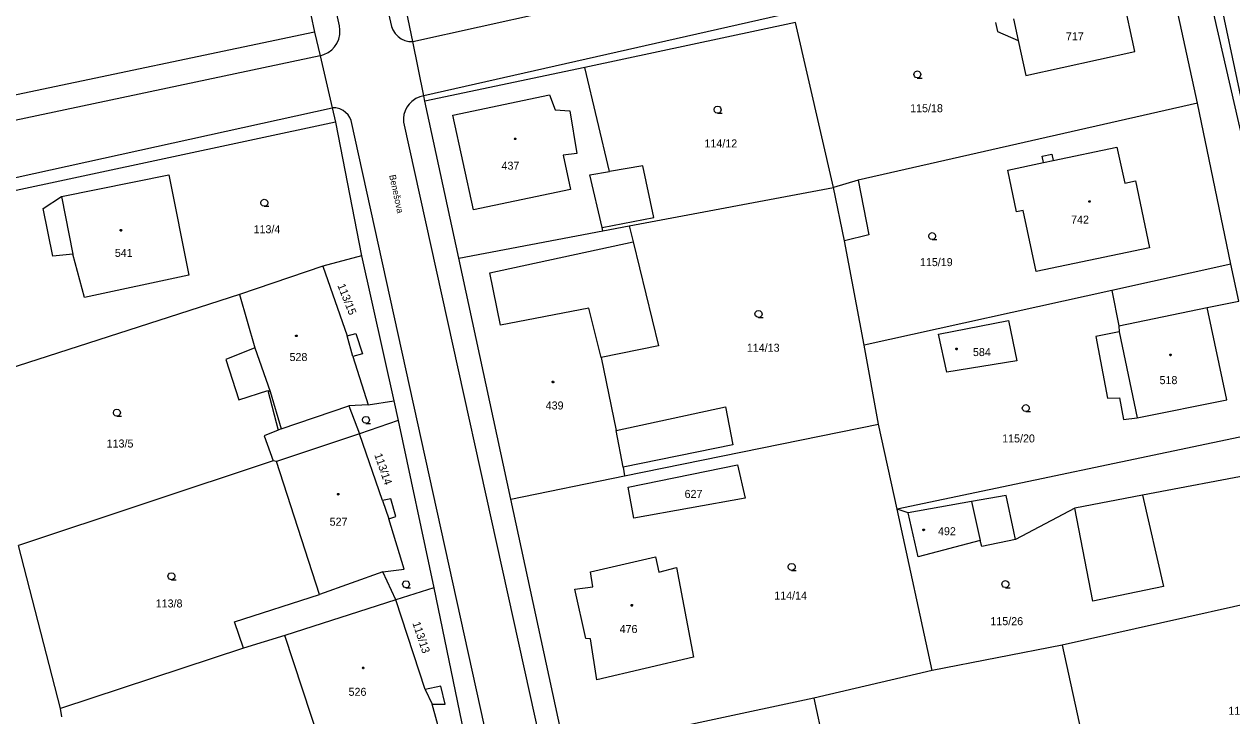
# Model space of a CAD drawing. Extents: x -757994 to -755874, y -1047691 to -1046119.
# Drawn here: x -756409.1 to -756280.8, y -1046951.8 to -1046878.4 of the extents above; entities that cross this region are included whole.
import ezdxf

# ---------------------------------------------------------------- set-up
doc = ezdxf.new("R2010")
doc.units = 0
doc.layers.add('katastrální mapa', color=7, linetype='Continuous')

msp = doc.modelspace()

# ---------------------------------------------------------------- linework, layer by layer
at = {"layer": 'katastrální mapa'}
for p, q in [((-756310.63, -1046740.64), (-756269.78, -1046934.1)), ((-756393.26, -1046773.82), (-756370.08, -1046878.6)), ((-756375.61, -1046878.54), (-756398, -1046775.71)), ((-756289.01, -1046849.81), (-756269.04, -1046937.62)), ((-756367.82, -1046880.2), (-756289.56, -1046862.86)), ((-756288.48, -1046868.3), (-756366.64, -1046885.96)), ((-756284.47, -1046886.76), (-756288.21, -1046869.66)), ((-756291.13, -1046881.27), (-756293.02, -1046872.66)), ((-756379.28, -1046874.3), (-756378.24, -1046879.22)), ((-756367.82, -1046880.2), (-756368.48, -1046876.97)), ((-756304.02, -1046877.8), (-756303.52, -1046880.1)), ((-756378.24, -1046879.22), (-756414.68, -1046886.88)), ((-756378.24, -1046879.22), (-756377.66, -1046881.72)), ((-756327.17, -1046878.19), (-756349.56, -1046882.95)), ((-756323.13, -1046895.69), (-756327.17, -1046878.19)), ((-756305.94, -1046878.2), (-756305.74, -1046879.13)), ((-756305.74, -1046879.13), (-756303.52, -1046880.1)), ((-756366.64, -1046885.96), (-756367.82, -1046880.2)), ((-756303.52, -1046880.1), (-756302.71, -1046883.81)), ((-756377.66, -1046881.72), (-756455.39, -1046898.22)), ((-756377.66, -1046881.72), (-756376.38, -1046887.23)), ((-756302.71, -1046883.81), (-756291.13, -1046881.27)), ((-756349.56, -1046882.95), (-756366.52, -1046886.55)), ((-756346.94, -1046894.01), (-756349.56, -1046882.95)), ((-756366.52, -1046886.55), (-756366.64, -1046885.96)), ((-756362.92, -1046903.22), (-756366.52, -1046886.55)), ((-756363.56, -1046888.02), (-756353.29, -1046885.85)), ((-756353.29, -1046885.85), (-756352.71, -1046887.45)), ((-756284.47, -1046886.76), (-756320.52, -1046894.94)), ((-756280.96, -1046903.84), (-756284.47, -1046886.76)), ((-756453.94, -1046904.33), (-756376.38, -1046887.23)), ((-756376.38, -1046887.23), (-756376.03, -1046888.76)), ((-756361.38, -1046898.09), (-756363.56, -1046888.02)), ((-756352.71, -1046887.45), (-756351.15, -1046887.55)), ((-756351.15, -1046887.55), (-756350.39, -1046892.08)), ((-756376.03, -1046888.76), (-756414.65, -1046897.03)), ((-756376.03, -1046888.76), (-756373.27, -1046902.96)), ((-756352.31, -1046988.69), (-756374.35, -1046888.59)), ((-756368.81, -1046888.76), (-756346.03, -1046991.81)), ((-756350.39, -1046892.08), (-756351.85, -1046892.27)), ((-756299.81, -1046892.85), (-756293.06, -1046891.43)), ((-756293.06, -1046891.43), (-756292.21, -1046895.24)), ((-756351.85, -1046892.27), (-756351.07, -1046895.92)), ((-756343.38, -1046893.4), (-756346.94, -1046894.01)), ((-756342.2, -1046898.88), (-756343.38, -1046893.4)), ((-756304.64, -1046893.86), (-756300.83, -1046893.06)), ((-756300.98, -1046892.37), (-756299.96, -1046892.15)), ((-756300.83, -1046893.06), (-756300.98, -1046892.37)), ((-756300.83, -1046893.06), (-756299.81, -1046892.85)), ((-756299.96, -1046892.15), (-756299.81, -1046892.85)), ((-756405.13, -1046896.65), (-756393.73, -1046894.36)), ((-756393.73, -1046894.36), (-756391.59, -1046905.02)), ((-756349.01, -1046894.37), (-756346.94, -1046894.01)), ((-756347.71, -1046899.94), (-756349.01, -1046894.37)), ((-756303.69, -1046898.29), (-756304.64, -1046893.86)), ((-756351.07, -1046895.92), (-756361.38, -1046898.09)), ((-756344.82, -1046899.79), (-756323.13, -1046895.69)), ((-756320.52, -1046894.94), (-756323.13, -1046895.69)), ((-756321.96, -1046901.38), (-756323.13, -1046895.69)), ((-756320.52, -1046894.94), (-756319.39, -1046900.73)), ((-756292.21, -1046895.24), (-756291.08, -1046895)), ((-756291.08, -1046895), (-756289.58, -1046902.11)), ((-756407.05, -1046897.94), (-756405.13, -1046896.65)), ((-756405.13, -1046896.65), (-756403.91, -1046902.78)), ((-756406.05, -1046903.01), (-756407.05, -1046897.94)), ((-756303, -1046898.14), (-756303.69, -1046898.29)), ((-756301.63, -1046904.61), (-756303, -1046898.14)), ((-756347.71, -1046899.94), (-756342.2, -1046898.88)), ((-756347.62, -1046900.32), (-756344.82, -1046899.79)), ((-756344.82, -1046899.79), (-756344.41, -1046901.47)), ((-756362.92, -1046903.22), (-756347.62, -1046900.32)), ((-756347.62, -1046900.32), (-756347.71, -1046899.94)), ((-756319.39, -1046900.73), (-756321.96, -1046901.38)), ((-756359.64, -1046904.77), (-756344.41, -1046901.47)), ((-756344.41, -1046901.47), (-756341.72, -1046912.53)), ((-756319.88, -1046912.45), (-756321.96, -1046901.38)), ((-756289.58, -1046902.11), (-756301.63, -1046904.61)), ((-756403.91, -1046902.78), (-756406.05, -1046903.01)), ((-756402.67, -1046907.39), (-756403.91, -1046902.78)), ((-756373.27, -1046902.96), (-756377.38, -1046904.07)), ((-756373.27, -1046902.96), (-756369.84, -1046918.35)), ((-756357.39, -1046928.78), (-756362.92, -1046903.22)), ((-756377.38, -1046904.07), (-756386.22, -1046907.08)), ((-756377.38, -1046904.07), (-756374.79, -1046911.44)), ((-756358.5, -1046910.33), (-756359.64, -1046904.77)), ((-756280.96, -1046903.84), (-756293.57, -1046906.63)), ((-756280.1, -1046907.77), (-756280.96, -1046903.84)), ((-756391.59, -1046905.02), (-756402.67, -1046907.39)), ((-756386.22, -1046907.08), (-756414.19, -1046916.08)), ((-756386.22, -1046907.08), (-756384.57, -1046912.72)), ((-756293.57, -1046906.63), (-756319.88, -1046912.45)), ((-756293.57, -1046906.63), (-756292.83, -1046910.39)), ((-756349.13, -1046908.5), (-756358.5, -1046910.33)), ((-756347.81, -1046913.76), (-756349.13, -1046908.5)), ((-756292.83, -1046910.39), (-756283.45, -1046908.46)), ((-756283.45, -1046908.46), (-756280.1, -1046907.77)), ((-756281.37, -1046918.24), (-756283.45, -1046908.46)), ((-756312, -1046911.29), (-756304.57, -1046909.82)), ((-756304.57, -1046909.82), (-756303.68, -1046914.09)), ((-756374.79, -1046911.44), (-756373.86, -1046911.21)), ((-756373.86, -1046911.21), (-756373.15, -1046913.35)), ((-756311.12, -1046915.31), (-756312, -1046911.29)), ((-756292.79, -1046911.04), (-756295.3, -1046911.53)), ((-756292.83, -1046910.39), (-756292.79, -1046911.04)), ((-756292.79, -1046911.04), (-756290.91, -1046920.17)), ((-756374.17, -1046913.64), (-756374.79, -1046911.44)), ((-756341.72, -1046912.53), (-756347.81, -1046913.76)), ((-756318.36, -1046920.83), (-756319.88, -1046912.45)), ((-756295.3, -1046911.53), (-756294.03, -1046918.06)), ((-756384.57, -1046912.72), (-756387.65, -1046913.96)), ((-756384.57, -1046912.72), (-756382.94, -1046917.35)), ((-756373.15, -1046913.35), (-756374.17, -1046913.64)), ((-756374.17, -1046913.64), (-756372.56, -1046918.78)), ((-756347.81, -1046913.76), (-756346.21, -1046921.5)), ((-756387.65, -1046913.96), (-756386.27, -1046918.25)), ((-756303.68, -1046914.09), (-756311.12, -1046915.31)), ((-756386.27, -1046918.25), (-756383.22, -1046917.27)), ((-756383.22, -1046917.27), (-756382.09, -1046921.47)), ((-756383.22, -1046917.27), (-756382.94, -1046917.35)), ((-756382.94, -1046917.35), (-756381.78, -1046921.34)), ((-756381.78, -1046921.34), (-756374.6, -1046918.9)), ((-756372.56, -1046918.78), (-756374.6, -1046918.9)), ((-756374.6, -1046918.9), (-756373.48, -1046921.86)), ((-756372.56, -1046918.78), (-756369.84, -1046918.35)), ((-756369.84, -1046918.35), (-756369.38, -1046920.43)), ((-756346.21, -1046921.5), (-756334.59, -1046918.98)), ((-756334.59, -1046918.98), (-756333.84, -1046923.03)), ((-756294.03, -1046918.06), (-756292.78, -1046918.02)), ((-756292.78, -1046918.02), (-756292.36, -1046920.32)), ((-756290.91, -1046920.17), (-756281.37, -1046918.24)), ((-756292.36, -1046920.32), (-756290.91, -1046920.17)), ((-756382.09, -1046921.47), (-756383.59, -1046922.06)), ((-756381.78, -1046921.34), (-756382.09, -1046921.47)), ((-756369.38, -1046920.43), (-756373.48, -1046921.86)), ((-756369.38, -1046920.43), (-756365.56, -1046938.21)), ((-756345.49, -1046925.39), (-756346.21, -1046921.5)), ((-756345.32, -1046926.32), (-756318.36, -1046920.83)), ((-756316.39, -1046929.84), (-756318.36, -1046920.83)), ((-756277.09, -1046921.59), (-756316.39, -1046929.84)), ((-756383.59, -1046922.06), (-756382.63, -1046924.73)), ((-756373.48, -1046921.86), (-756382.27, -1046924.8)), ((-756371.03, -1046928.94), (-756373.48, -1046921.86)), ((-756333.84, -1046923.03), (-756345.49, -1046925.39)), ((-756382.63, -1046924.73), (-756409.67, -1046933.7)), ((-756382.27, -1046924.8), (-756382.63, -1046924.73)), ((-756377.7, -1046938.9), (-756382.27, -1046924.8)), ((-756345.49, -1046925.39), (-756345.32, -1046926.32)), ((-756344.94, -1046927.52), (-756333.33, -1046925.14)), ((-756333.33, -1046925.14), (-756332.51, -1046928.69)), ((-756357.39, -1046928.78), (-756345.32, -1046926.32)), ((-756276.17, -1046925.69), (-756290.34, -1046928.38)), ((-756344.34, -1046930.8), (-756344.94, -1046927.52)), ((-756370.14, -1046928.75), (-756371.03, -1046928.94)), ((-756371.03, -1046928.94), (-756370.35, -1046930.87)), ((-756369.62, -1046930.63), (-756370.14, -1046928.75)), ((-756351.61, -1046955.54), (-756357.39, -1046928.78)), ((-756332.51, -1046928.69), (-756344.34, -1046930.8)), ((-756308.49, -1046929.05), (-756315.21, -1046930.24)), ((-756304.81, -1046928.4), (-756308.49, -1046929.05)), ((-756308.49, -1046929.05), (-756307.56, -1046933.17)), ((-756303.99, -1046932.23), (-756304.81, -1046928.4)), ((-756290.34, -1046928.38), (-756297.51, -1046929.74)), ((-756290.34, -1046928.38), (-756288.09, -1046938.05)), ((-756315.21, -1046930.24), (-756316.39, -1046929.84)), ((-756312.65, -1046946.99), (-756316.39, -1046929.84)), ((-756314.15, -1046934.91), (-756315.21, -1046930.24)), ((-756297.51, -1046929.74), (-756303.81, -1046933.07)), ((-756295.61, -1046939.63), (-756297.51, -1046929.74)), ((-756370.35, -1046930.87), (-756369.62, -1046930.63)), ((-756368.72, -1046936.21), (-756370.35, -1046930.87)), ((-756303.81, -1046933.07), (-756307.39, -1046933.81)), ((-756303.81, -1046933.07), (-756303.99, -1046932.23)), ((-756405.21, -1046951.01), (-756409.67, -1046933.7)), ((-756307.56, -1046933.17), (-756314.15, -1046934.91)), ((-756307.39, -1046933.81), (-756307.56, -1046933.17)), ((-756348.94, -1046936.52), (-756342.03, -1046934.9)), ((-756342.03, -1046934.9), (-756341.69, -1046936.53)), ((-756371, -1046936.5), (-756377.7, -1046938.9)), ((-756371, -1046936.5), (-756368.72, -1046936.21)), ((-756369.6, -1046939.49), (-756371, -1046936.5)), ((-756348.68, -1046938.09), (-756348.94, -1046936.52)), ((-756341.69, -1046936.53), (-756339.82, -1046936.05)), ((-756339.82, -1046936.05), (-756338.01, -1046945.57)), ((-756365.56, -1046938.21), (-756369.6, -1046939.49)), ((-756365.56, -1046938.21), (-756361.96, -1046955.74)), ((-756350.62, -1046938.34), (-756348.68, -1046938.09)), ((-756288.09, -1046938.05), (-756295.61, -1046939.63)), ((-756386.73, -1046941.82), (-756377.7, -1046938.9)), ((-756369.6, -1046939.49), (-756381.41, -1046943.28)), ((-756366.51, -1046949), (-756369.6, -1046939.49)), ((-756349.42, -1046943.58), (-756350.62, -1046938.34)), ((-756273.27, -1046938.57), (-756298.86, -1046944.31)), ((-756385.78, -1046944.6), (-756386.73, -1046941.82)), ((-756381.41, -1046943.28), (-756385.78, -1046944.6)), ((-756376.83, -1046957.1), (-756381.41, -1046943.28)), ((-756385.78, -1046944.6), (-756405.21, -1046951.01)), ((-756348.94, -1046943.61), (-756349.42, -1046943.58)), ((-756348.26, -1046947.98), (-756348.94, -1046943.61)), ((-756298.86, -1046944.31), (-756312.65, -1046946.99)), ((-756298.86, -1046944.31), (-756294.36, -1046964.81)), ((-756338.01, -1046945.57), (-756348.26, -1046947.98)), ((-756312.65, -1046946.99), (-756325.22, -1046949.93)), ((-756364.84, -1046948.64), (-756366.51, -1046949)), ((-756366.51, -1046949), (-756365.76, -1046950.54)), ((-756364.36, -1046950.54), (-756364.84, -1046948.64)), ((-756405.07, -1046951.9), (-756405.21, -1046951.01)), ((-756364.88, -1046953.79), (-756365.76, -1046950.54)), ((-756365.76, -1046950.54), (-756364.36, -1046950.54)), ((-756325.22, -1046949.93), (-756351.61, -1046955.54)), ((-756325.22, -1046949.93), (-756317.82, -1046983.8))]:
    msp.add_line(p, q, dxfattribs=at)
for points in [[(-756377.66, -1046881.72), (-756377.24, -1046881.6), (-756376.8, -1046881.38), (-756376.41, -1046881.08), (-756376.12, -1046880.76), (-756375.87, -1046880.4), (-756375.68, -1046879.95), (-756375.57, -1046879.47), (-756375.55, -1046878.97), (-756375.61, -1046878.54)], [(-756370.08, -1046878.6), (-756369.94, -1046878.98), (-756369.7, -1046879.37), (-756369.38, -1046879.69), (-756369.04, -1046879.92), (-756368.67, -1046880.09), (-756368.23, -1046880.19), (-756367.82, -1046880.2)], [(-756314.23, -1046884.07), (-756314.42, -1046884.02), (-756314.55, -1046883.89), (-756314.6, -1046883.7), (-756314.55, -1046883.51), (-756314.42, -1046883.38), (-756314.23, -1046883.33), (-756314.05, -1046883.38), (-756313.92, -1046883.51), (-756313.86, -1046883.71), (-756313.92, -1046883.9), (-756314.05, -1046884.03), (-756314.24, -1046884.08), (-756313.74, -1046884.08)], [(-756366.64, -1046885.96), (-756367.06, -1046886.07), (-756367.5, -1046886.27), (-756367.9, -1046886.56), (-756368.2, -1046886.87), (-756368.44, -1046887.19), (-756368.62, -1046887.56), (-756368.75, -1046887.95), (-756368.81, -1046888.36), (-756368.81, -1046888.76)], [(-756374.35, -1046888.59), (-756374.49, -1046888.27), (-756374.69, -1046887.98), (-756374.94, -1046887.73), (-756375.22, -1046887.53), (-756375.57, -1046887.35), (-756375.99, -1046887.25), (-756376.38, -1046887.23)], [(-756335.44, -1046887.81), (-756335.63, -1046887.76), (-756335.76, -1046887.62), (-756335.82, -1046887.44), (-756335.76, -1046887.26), (-756335.63, -1046887.12), (-756335.45, -1046887.07), (-756335.26, -1046887.12), (-756335.12, -1046887.26), (-756335.08, -1046887.45), (-756335.12, -1046887.64), (-756335.26, -1046887.77), (-756335.45, -1046887.82), (-756334.95, -1046887.82)], [(-756383.57, -1046897.69), (-756383.76, -1046897.64), (-756383.9, -1046897.5), (-756383.95, -1046897.32), (-756383.9, -1046897.14), (-756383.76, -1046897), (-756383.58, -1046896.95), (-756383.39, -1046897), (-756383.25, -1046897.14), (-756383.21, -1046897.33), (-756383.25, -1046897.51), (-756383.39, -1046897.65), (-756383.58, -1046897.7), (-756383.08, -1046897.7)], [(-756312.65, -1046901.23), (-756312.84, -1046901.18), (-756312.98, -1046901.04), (-756313.03, -1046900.86), (-756312.98, -1046900.68), (-756312.84, -1046900.54), (-756312.66, -1046900.49), (-756312.47, -1046900.54), (-756312.34, -1046900.68), (-756312.29, -1046900.87), (-756312.34, -1046901.05), (-756312.47, -1046901.19), (-756312.66, -1046901.24), (-756312.16, -1046901.24)], [(-756331.1, -1046909.5), (-756331.29, -1046909.45), (-756331.43, -1046909.32), (-756331.48, -1046909.13), (-756331.43, -1046908.95), (-756331.29, -1046908.81), (-756331.1, -1046908.76), (-756330.92, -1046908.81), (-756330.78, -1046908.95), (-756330.73, -1046909.14), (-756330.78, -1046909.33), (-756330.92, -1046909.46), (-756331.11, -1046909.51), (-756330.61, -1046909.51)], [(-756302.71, -1046919.49), (-756302.9, -1046919.44), (-756303.03, -1046919.3), (-756303.09, -1046919.12), (-756303.03, -1046918.94), (-756302.9, -1046918.8), (-756302.72, -1046918.75), (-756302.53, -1046918.8), (-756302.4, -1046918.94), (-756302.35, -1046919.12), (-756302.4, -1046919.32), (-756302.53, -1046919.45), (-756302.72, -1046919.5), (-756302.22, -1046919.5)], [(-756399.23, -1046919.98), (-756399.42, -1046919.93), (-756399.55, -1046919.79), (-756399.6, -1046919.61), (-756399.55, -1046919.43), (-756399.42, -1046919.29), (-756399.23, -1046919.24), (-756399.05, -1046919.29), (-756398.92, -1046919.43), (-756398.86, -1046919.62), (-756398.92, -1046919.8), (-756399.05, -1046919.94), (-756399.24, -1046919.99), (-756398.74, -1046919.99)], [(-756372.78, -1046920.74), (-756372.97, -1046920.69), (-756373.1, -1046920.55), (-756373.16, -1046920.37), (-756373.1, -1046920.19), (-756372.97, -1046920.05), (-756372.79, -1046920), (-756372.6, -1046920.05), (-756372.47, -1046920.19), (-756372.42, -1046920.38), (-756372.47, -1046920.57), (-756372.6, -1046920.7), (-756372.79, -1046920.75), (-756372.29, -1046920.75)], [(-756327.58, -1046936.35), (-756327.77, -1046936.3), (-756327.91, -1046936.17), (-756327.96, -1046935.98), (-756327.91, -1046935.79), (-756327.77, -1046935.66), (-756327.59, -1046935.61), (-756327.4, -1046935.66), (-756327.26, -1046935.79), (-756327.22, -1046935.99), (-756327.26, -1046936.18), (-756327.4, -1046936.31), (-756327.59, -1046936.36), (-756327.09, -1046936.36)], [(-756393.44, -1046937.34), (-756393.63, -1046937.29), (-756393.76, -1046937.16), (-756393.82, -1046936.97), (-756393.76, -1046936.78), (-756393.63, -1046936.65), (-756393.45, -1046936.6), (-756393.26, -1046936.65), (-756393.12, -1046936.78), (-756393.08, -1046936.98), (-756393.12, -1046937.17), (-756393.26, -1046937.3), (-756393.45, -1046937.35), (-756392.95, -1046937.35)], [(-756368.53, -1046938.2), (-756368.72, -1046938.15), (-756368.85, -1046938.01), (-756368.91, -1046937.83), (-756368.85, -1046937.65), (-756368.72, -1046937.51), (-756368.54, -1046937.46), (-756368.35, -1046937.51), (-756368.22, -1046937.65), (-756368.17, -1046937.84), (-756368.22, -1046938.02), (-756368.35, -1046938.16), (-756368.54, -1046938.21), (-756368.04, -1046938.21)], [(-756304.88, -1046938.18), (-756305.07, -1046938.13), (-756305.21, -1046938), (-756305.26, -1046937.81), (-756305.21, -1046937.62), (-756305.07, -1046937.49), (-756304.89, -1046937.44), (-756304.7, -1046937.49), (-756304.57, -1046937.62), (-756304.52, -1046937.82), (-756304.57, -1046938.01), (-756304.7, -1046938.14), (-756304.89, -1046938.19), (-756304.39, -1046938.19)]]:
    msp.add_lwpolyline(points, dxfattribs=at)
for points in [[(-756356.95, -1046890.45), (-756356.9, -1046890.46), (-756356.88, -1046890.5), (-756356.86, -1046890.53), (-756356.88, -1046890.58), (-756356.92, -1046890.61), (-756356.95, -1046890.62), (-756356.99, -1046890.6), (-756357.02, -1046890.57), (-756357.03, -1046890.53), (-756357.02, -1046890.49), (-756356.98, -1046890.45)], [(-756295.95, -1046897.11), (-756295.9, -1046897.12), (-756295.88, -1046897.16), (-756295.86, -1046897.19), (-756295.88, -1046897.23), (-756295.92, -1046897.27), (-756295.95, -1046897.27), (-756295.99, -1046897.26), (-756296.02, -1046897.23), (-756296.03, -1046897.19), (-756296.02, -1046897.15), (-756295.98, -1046897.11)], [(-756398.8, -1046900.17), (-756398.75, -1046900.18), (-756398.73, -1046900.22), (-756398.72, -1046900.25), (-756398.73, -1046900.29), (-756398.77, -1046900.33), (-756398.8, -1046900.34), (-756398.85, -1046900.32), (-756398.88, -1046900.29), (-756398.89, -1046900.25), (-756398.88, -1046900.21), (-756398.84, -1046900.17)], [(-756380.17, -1046911.37), (-756380.12, -1046911.38), (-756380.1, -1046911.42), (-756380.09, -1046911.45), (-756380.1, -1046911.49), (-756380.14, -1046911.53), (-756380.17, -1046911.53), (-756380.22, -1046911.52), (-756380.25, -1046911.49), (-756380.26, -1046911.45), (-756380.25, -1046911.41), (-756380.21, -1046911.37)], [(-756310.06, -1046912.76), (-756310.01, -1046912.77), (-756309.99, -1046912.82), (-756309.98, -1046912.85), (-756309.99, -1046912.9), (-756310.03, -1046912.93), (-756310.06, -1046912.94), (-756310.1, -1046912.92), (-756310.14, -1046912.89), (-756310.15, -1046912.85), (-756310.14, -1046912.8), (-756310.1, -1046912.77)], [(-756287.35, -1046913.4), (-756287.3, -1046913.41), (-756287.27, -1046913.45), (-756287.26, -1046913.48), (-756287.27, -1046913.52), (-756287.32, -1046913.56), (-756287.35, -1046913.57), (-756287.4, -1046913.55), (-756287.43, -1046913.52), (-756287.44, -1046913.48), (-756287.43, -1046913.44), (-756287.39, -1046913.4)], [(-756352.93, -1046916.26), (-756352.88, -1046916.27), (-756352.85, -1046916.32), (-756352.85, -1046916.35), (-756352.85, -1046916.4), (-756352.9, -1046916.43), (-756352.93, -1046916.44), (-756352.98, -1046916.42), (-756353.01, -1046916.39), (-756353.02, -1046916.35), (-756353.01, -1046916.3), (-756352.97, -1046916.27)], [(-756375.73, -1046928.19), (-756375.68, -1046928.2), (-756375.66, -1046928.24), (-756375.65, -1046928.27), (-756375.66, -1046928.32), (-756375.7, -1046928.35), (-756375.73, -1046928.36), (-756375.77, -1046928.34), (-756375.8, -1046928.31), (-756375.82, -1046928.27), (-756375.8, -1046928.23), (-756375.76, -1046928.19)], [(-756313.57, -1046931.97), (-756313.52, -1046931.98), (-756313.49, -1046932.02), (-756313.48, -1046932.05), (-756313.49, -1046932.1), (-756313.53, -1046932.13), (-756313.57, -1046932.14), (-756313.61, -1046932.12), (-756313.65, -1046932.09), (-756313.66, -1046932.05), (-756313.65, -1046932.01), (-756313.6, -1046931.97)], [(-756344.54, -1046939.98), (-756344.49, -1046939.99), (-756344.47, -1046940.04), (-756344.46, -1046940.07), (-756344.47, -1046940.12), (-756344.51, -1046940.15), (-756344.54, -1046940.16), (-756344.59, -1046940.14), (-756344.61, -1046940.11), (-756344.62, -1046940.07), (-756344.61, -1046940.02), (-756344.58, -1046939.99)], [(-756373.08, -1046946.62), (-756373.03, -1046946.64), (-756373, -1046946.68), (-756372.99, -1046946.71), (-756373, -1046946.75), (-756373.04, -1046946.79), (-756373.08, -1046946.79), (-756373.12, -1046946.78), (-756373.16, -1046946.75), (-756373.17, -1046946.71), (-756373.16, -1046946.67), (-756373.11, -1046946.63)]]:
    msp.add_lwpolyline(points, close=True, dxfattribs=at)

# ---------------------------------------------------------------- texts
for s, p in [('717', (-756298.46, -1046880.08)), ('115/18', (-756315, -1046887.71)), ('114/12', (-756336.84, -1046891.45)), ('437', (-756358.39, -1046893.81)), ('113/4', (-756384.72, -1046900.56)), ('742', (-756297.91, -1046899.54)), ('541', (-756399.45, -1046903.07)), ('115/19', (-756313.96, -1046904.05)), ('114/13', (-756332.34, -1046913.14)), ('528', (-756380.9, -1046914.13)), ('584', (-756308.33, -1046913.6)), ('518', (-756288.52, -1046916.58)), ('439', (-756353.7, -1046919.27)), ('113/5', (-756400.32, -1046923.31)), ('115/20', (-756305.23, -1046922.77)), ('627', (-756338.95, -1046928.66)), ('527', (-756376.64, -1046931.61)), ('492', (-756312.04, -1046932.62)), ('113/8', (-756395.11, -1046940.29)), ('114/14', (-756329.43, -1046939.45)), ('476', (-756345.85, -1046943)), ('115/26', (-756306.48, -1046942.17)), ('526', (-756374.63, -1046949.67)), ('115/12', (-756281.21, -1046951.68))]:
    msp.add_text(s, height=0.85, dxfattribs=at).set_placement(p)
for s, height, rotation, p in [('Benešova', 0.7, 282.0671, (-756370.32, -1046894.42)), ('113/15', 0.85, 291.6928, (-756375.83, -1046906.1)), ('113/14', 0.85, 289.0572, (-756371.91, -1046924.08)), ('113/13', 0.85, 288.427, (-756367.86, -1046941.95))]:
    msp.add_text(s, height=height, rotation=rotation, dxfattribs=at).set_placement(p)

doc.saveas('drawing.dxf')
